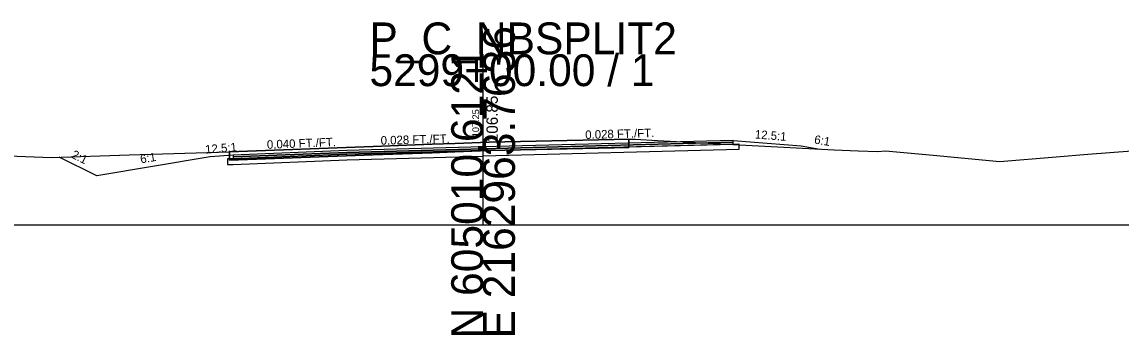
# Model space of a CAD drawing. Extents: x -26 to 1303, y -10 to 12038.
# Drawn here: x 109.4 to 206.1, y 9990.3 to 10017.8 of the extents above; entities that cross this region are included whole.
import ezdxf

# ---------------------------------------------------------------- set-up
doc = ezdxf.new("R2010")
doc.units = 0
for name, color, linetype in [('RD_GPK_XS_Cell', 7, 'Continuous'), ('RD_XS_Base', 7, 'Continuous'), ('RD_XS_ExGround', 7, 'Continuous'), ('RD_XS_ExPaveRet', 7, 'Continuous'), ('RD_XS_Greenside', 7, 'Continuous'), ('RD_XS_Pave', 7, 'Continuous'), ('RD_XS_PaveOvlay_CP', 7, 'Continuous'), ('RD_XS_TieSlope', 7, 'Continuous'), ('RD_XS_TX_Elev_EX', 7, 'Continuous'), ('RD_XS_TX_Elev_PR', 7, 'Continuous'), ('RD_XS_TX_ShdSlope', 7, 'Continuous'), ('RD_XS_TX_Slope', 7, 'Continuous')]:
    doc.layers.add(name, color=color, linetype=linetype)

msp = doc.modelspace()

# ---------------------------------------------------------------- linework, layer by layer
at = {"layer": 'RD_GPK_XS_Cell'}
for p, q in [((150, 10000), (150, 10015)), ((0, 10000), (150, 10000)), ((150, 10000), (300, 10000))]:
    msp.add_line(p, q, dxfattribs=at)
at = {"layer": 'RD_XS_Base'}
for p, q in [((138, 10006.216), (128, 10005.816)), ((150, 10006.528), (138, 10006.216)), ((138, 10006.216), (138, 10006.216)), ((150, 10006.528), (172.5, 10007.113)), ((150, 10006.028), (150, 10006.687)), ((150, 10006.687), (150, 10006.687)), ((150, 10006.687), (150, 10006.687)), ((150, 10006.687), (150, 10006.528)), ((172.5, 10006.613), (150, 10006.028)), ((150, 10006.528), (150, 10006.528)), ((150, 10006.028), (150, 10006.528)), ((150, 10006.528), (150, 10006.528)), ((150, 10006.528), (150, 10006.528)), ((172, 10007.1), (172, 10007.1)), ((172, 10007.1), (172, 10007.1)), ((172, 10007.1), (172, 10007.1)), ((172, 10006.6), (172, 10006.6)), ((172, 10006.6), (172, 10006.6)), ((172.5, 10007.113), (172.5, 10006.613)), ((172.5, 10007.08), (172.5, 10007.08)), ((128, 10005.816), (127.5, 10005.796)), ((127.5, 10005.796), (127.5, 10005.796)), ((127.5, 10005.796), (127.5, 10005.296)), ((127.5, 10005.296), (128, 10005.316)), ((128, 10005.816), (128, 10005.816)), ((128, 10005.316), (138, 10005.716)), ((128, 10005.316), (128, 10005.316)), ((138, 10005.716), (150, 10006.028)), ((138, 10005.716), (138, 10005.716)), ((150, 10006.028), (150, 10006.028))]:
    msp.add_line(p, q, dxfattribs=at)
at = {"layer": 'RD_XS_ExGround'}
msp.add_lwpolyline([(105.909, 10006.154), (112.035, 10005.928), (118.866, 10006.156), (127.688, 10006.425), (140.342, 10006.893), (145.516, 10007.088), (147.509, 10007.156), (150.536, 10007.273), (161.544, 10007.514), (162.822, 10007.547), (163.388, 10007.544), (165.349, 10007.421), (180.879, 10006.601), (183.019, 10006.5), (184.74, 10006.456), (185.419, 10006.503), (189.594, 10006.125), (195.466, 10005.573), (200.434, 10005.989), (203.207, 10006.202), (207.088, 10006.507)], dxfattribs=at)
at = {"layer": 'RD_XS_ExPaveRet'}
for points in [[(162.822, 10007.547), (162.822, 10007.547), (162.822, 10006.797), (162.822, 10006.797), (161.544, 10006.764), (161.544, 10006.764), (150.536, 10006.523), (150.536, 10006.523), (147.509, 10006.406), (147.509, 10006.406), (145.516, 10006.338), (145.516, 10006.338), (140.342, 10006.143), (140.342, 10006.143), (127.688, 10005.675), (127.688, 10006.425), (127.688, 10006.425), (140.342, 10006.893), (140.342, 10006.893), (145.516, 10007.088), (145.516, 10007.088), (147.509, 10007.156), (147.509, 10007.156), (150.536, 10007.273), (150.536, 10007.273), (161.544, 10007.514), (161.544, 10007.514), (162.822, 10007.547), (162.822, 10007.547)], [(161.544, 10007.514), (150.536, 10007.273), (147.509, 10007.156), (145.516, 10007.088), (140.342, 10006.893), (127.688, 10006.425), (127.688, 10005.675), (140.342, 10006.143), (145.516, 10006.338), (147.509, 10006.406), (150.536, 10006.523), (161.544, 10006.764), (162.822, 10006.797), (162.822, 10007.547), (161.544, 10007.514)]]:
    msp.add_lwpolyline(points, dxfattribs=at)
at = {"layer": 'RD_XS_Greenside'}
for p, q in [((178, 10006.938), (179.619, 10006.668)), ((116, 10004.307), (112.712, 10005.951)), ((126, 10005.974), (116, 10004.307))]:
    msp.add_line(p, q, dxfattribs=at)
at = {"layer": 'RD_XS_Pave'}
for p, q in [((172, 10007.418), (150, 10006.846)), ((172, 10007.259), (150, 10006.687)), ((150, 10006.687), (172, 10007.259)), ((172, 10007.259), (172, 10007.418)), ((172, 10007.418), (172, 10007.418)), ((172, 10007.418), (172, 10007.418)), ((172, 10007.418), (172, 10007.418)), ((172, 10007.1), (172, 10007.259)), ((172, 10007.259), (172, 10007.259)), ((172, 10007.259), (172, 10007.259)), ((172, 10007.259), (172, 10007.259)), ((172, 10007.259), (172, 10007.259)), ((172, 10007.259), (172, 10007.259)), ((138, 10006.534), (128, 10006.134)), ((128, 10005.975), (138, 10006.375)), ((138, 10006.375), (128, 10005.975)), ((128, 10005.816), (138, 10006.216)), ((150, 10006.846), (138, 10006.534)), ((138, 10006.375), (150, 10006.687)), ((150, 10006.687), (138, 10006.375)), ((138, 10006.534), (138, 10006.534)), ((138, 10006.216), (150, 10006.528)), ((138, 10006.375), (138, 10006.375)), ((138, 10006.375), (138, 10006.375)), ((138, 10006.216), (138, 10006.216)), ((150, 10006.528), (172, 10007.1)), ((150, 10006.846), (150, 10006.846)), ((150, 10006.687), (150, 10006.687)), ((150, 10006.687), (150, 10006.687)), ((150, 10006.687), (150, 10006.528)), ((150, 10006.687), (150, 10006.687)), ((150, 10006.528), (150, 10006.687)), ((150, 10006.687), (150, 10006.687)), ((150, 10006.687), (150, 10006.687)), ((150, 10006.528), (150, 10006.528)), ((150, 10006.528), (150, 10006.528)), ((172, 10007.1), (172, 10007.1)), ((172, 10007.1), (172, 10007.1)), ((128, 10006.134), (128, 10006.134)), ((128, 10006.134), (128, 10005.975)), ((128, 10005.975), (128, 10005.975)), ((128, 10005.975), (128, 10005.816))]:
    msp.add_line(p, q, dxfattribs=at)
at = {"layer": 'RD_XS_PaveOvlay_CP'}
for p, q in [((172, 10007.418), (150, 10006.846)), ((172, 10007.418), (172, 10007.418)), ((172, 10007.418), (172, 10007.418)), ((138, 10006.534), (128, 10006.134)), ((150, 10006.846), (138, 10006.534)), ((138, 10006.534), (138, 10006.534)), ((150, 10006.846), (150, 10006.846))]:
    msp.add_line(p, q, dxfattribs=at)
at = {"layer": 'RD_XS_TieSlope'}
for p, q in [((172, 10007.418), (178, 10006.938)), ((128, 10006.134), (126, 10005.974))]:
    msp.add_line(p, q, dxfattribs=at)

# ---------------------------------------------------------------- texts
at = {"layer": 'RD_GPK_XS_Cell'}
for s, p in [('P_C_NBSPLIT2', (140, 10015)), ('5299+00.00 / 1', (140, 10012.2))]:
    msp.add_text(s, height=2.8, dxfattribs=at).set_placement(p)
for s, p in [('E 2162963.7636', (152.8, 9990)), ('N 605010.6121', (150, 9990))]:
    msp.add_text(s, height=2.8, rotation=90, dxfattribs=at).set_placement(p)
at = {"layer": 'RD_XS_TX_Elev_EX'}
msp.add_text('107.25', height=0.6, rotation=90, dxfattribs=at).set_placement((149.653, 10007.708))
at = {"layer": 'RD_XS_TX_Elev_PR'}
msp.add_text('106.85', height=1, rotation=90, dxfattribs=at).set_placement((151.297, 10007.27))
at = {"layer": 'RD_XS_TX_ShdSlope'}
for rotation, p in [(355.42608, (173.893, 10007.603)), (4.57392, (125.578, 10006.259))]:
    msp.add_text('12.5:1', height=0.75, rotation=rotation, dxfattribs=at).set_placement(p)
at = {"layer": 'RD_XS_TX_Slope'}
for s, rotation, p in [('0.028 FT./FT.', 1.60386, (158.999, 10007.547)), ('0.040 FT./FT.', 2.29061, (130.995, 10006.679)), ('0.028 FT./FT.', 1.60386, (140.999, 10007.043)), ('6:1', 350.53582, (179.099, 10007.159)), ('2:1', 333.43495, (113.716, 10005.937)), ('6:1', 9.46418, (119.893, 10005.4))]:
    msp.add_text(s, height=0.75, rotation=rotation, dxfattribs=at).set_placement(p)

doc.saveas('drawing.dxf')
